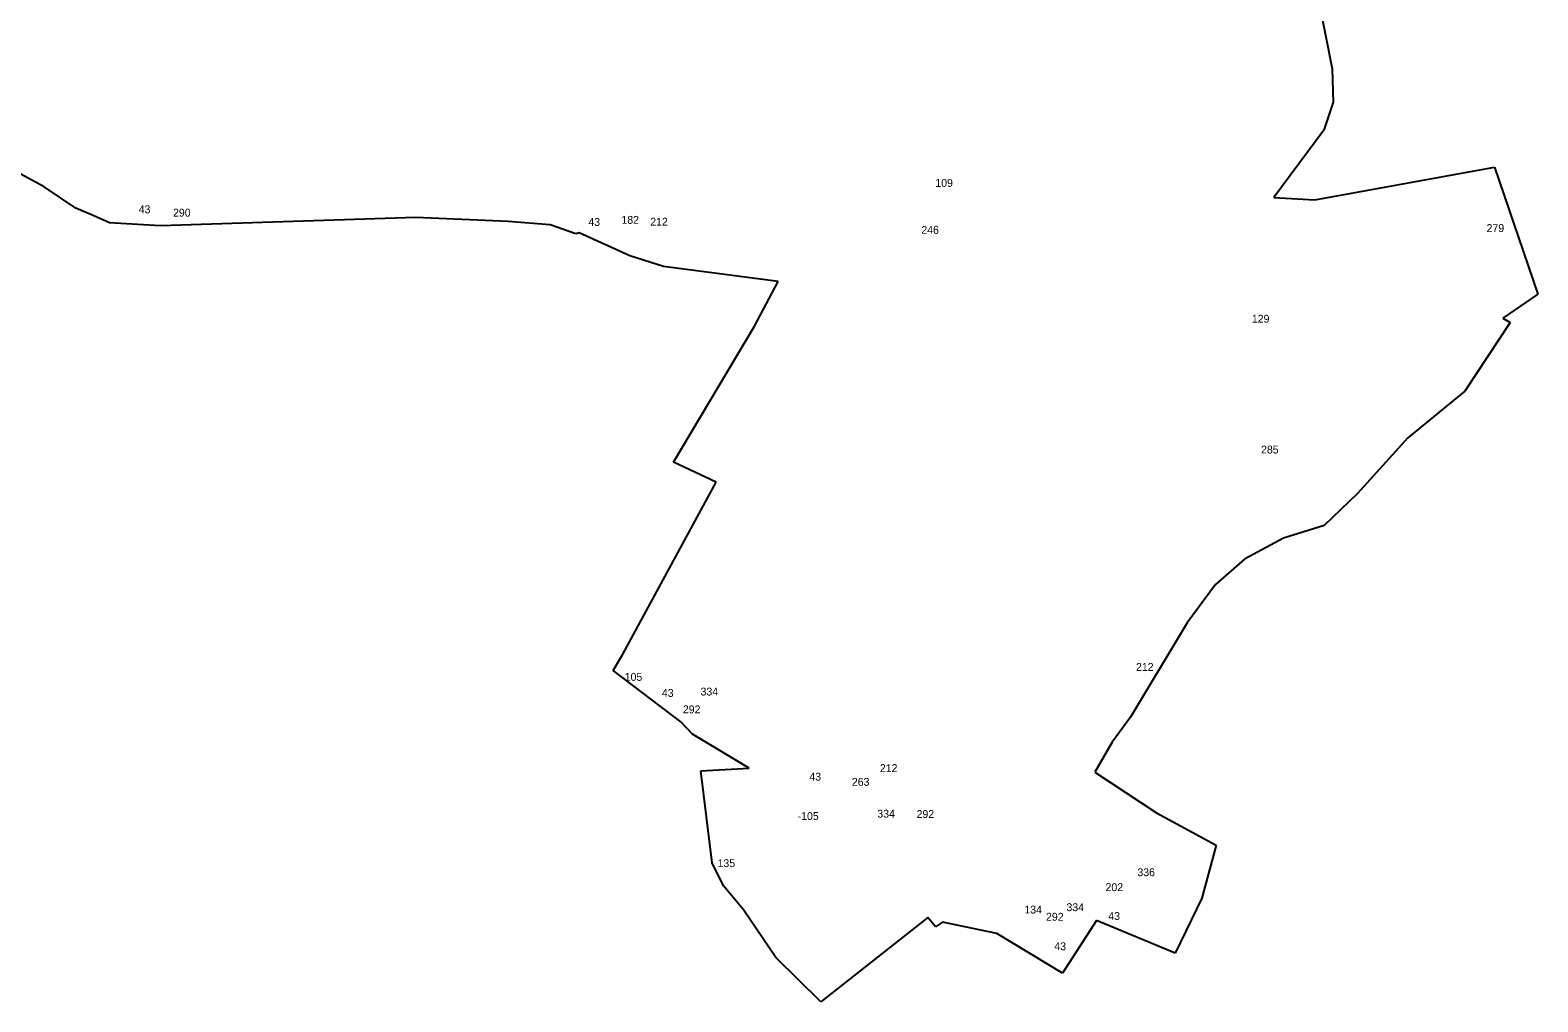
# Model space of a CAD drawing. Extents: x -780116 to -776974, y -980293 to -977147.
# Drawn here: x -778640 to -777427, y -980293 to -979511 of the extents above; entities that cross this region are included whole.
import ezdxf

# ---------------------------------------------------------------- set-up
doc = ezdxf.new("R2010")
doc.units = 0
doc.layers.add('Vrstva 15', color=7, linetype='Continuous')
doc.layers.add('Vrstva 24', color=7, linetype='Continuous')

msp = doc.modelspace()

# ---------------------------------------------------------------- linework, layer by layer
at = {"layer": 'Vrstva 15'}
for p, q in [((-777602.89, -979490.63), (-777592.69, -979542.23)), ((-777592.69, -979542.23), (-777591.82, -979569.04)), ((-777591.82, -979569.04), (-777599.39, -979591.42)), ((-777599.39, -979591.42), (-777639.46, -979645.78)), ((-778628.77, -979637.15), (-778699.86, -979598.82)), ((-777606.53, -979647.67), (-777462.01, -979621.3)), ((-777462.01, -979621.3), (-777427.18, -979723.33)), ((-778603.27, -979654.2), (-778628.77, -979637.15)), ((-778588.74, -979660.54), (-778603.27, -979654.2)), ((-777639.46, -979645.78), (-777606.53, -979647.67)), ((-778576.21, -979665.93), (-778588.74, -979660.54)), ((-778534.99, -979668.48), (-778576.21, -979665.93)), ((-778329.86, -979661.77), (-778534.99, -979668.48)), ((-778255.41, -979664.91), (-778329.86, -979661.77)), ((-778221.69, -979667.59), (-778255.41, -979664.91)), ((-778201.08, -979674.89), (-778221.69, -979667.59)), ((-778198.45, -979674.01), (-778201.08, -979674.89)), ((-778157.66, -979692.67), (-778198.45, -979674.01)), ((-778130.56, -979701.05), (-778157.66, -979692.67)), ((-778038.34, -979713.26), (-778130.56, -979701.05)), ((-778057.28, -979749.18), (-778038.34, -979713.26)), ((-777427.18, -979723.33), (-777455.45, -979742.86)), ((-778122.56, -979858.68), (-778057.28, -979749.18)), ((-777449.47, -979746.21), (-777486.03, -979801.53)), ((-777455.45, -979742.86), (-777449.47, -979746.21)), ((-777486.03, -979801.53), (-777531.7, -979838.88)), ((-777531.7, -979838.88), (-777572.14, -979883.69)), ((-778088.04, -979874.57), (-778122.56, -979858.68)), ((-778163.21, -980013.03), (-778088.04, -979874.57)), ((-777572.14, -979883.69), (-777599.16, -979909.56)), ((-777599.16, -979909.56), (-777631.73, -979919.62)), ((-777631.73, -979919.62), (-777663.2, -979936.6)), ((-777663.2, -979936.6), (-777686.51, -979956.94)), ((-777686.51, -979956.94), (-777709.24, -979987.76)), ((-777709.24, -979987.76), (-777754.84, -980063.63)), ((-778171.07, -980026.07), (-778163.21, -980013.03)), ((-778116.44, -980067.5), (-778171.07, -980026.07)), ((-778107.05, -980077.41), (-778116.44, -980067.5)), ((-777754.84, -980063.63), (-777769.55, -980083.67)), ((-778061.66, -980104.56), (-778107.05, -980077.41)), ((-777769.55, -980083.67), (-777783.54, -980107.79)), ((-778100.41, -980106.9), (-778061.66, -980104.56)), ((-778091.39, -980180.72), (-778100.41, -980106.9)), ((-777783.54, -980107.79), (-777734.01, -980140.52)), ((-777734.01, -980140.52), (-777685.89, -980166.64)), ((-777685.89, -980166.64), (-777697.58, -980209.29)), ((-778082.21, -980199.23), (-778091.39, -980180.72)), ((-778066.04, -980218.76), (-778082.21, -980199.23)), ((-777697.58, -980209.29), (-777718.93, -980253.63)), ((-778040.25, -980257.09), (-778066.04, -980218.76)), ((-777917.87, -980224.74), (-778003.83, -980292.65)), ((-777911.6, -980232.32), (-777917.87, -980224.74)), ((-777782.08, -980227.1), (-777809.62, -980269.63)), ((-777718.93, -980253.63), (-777782.08, -980227.1)), ((-777906.21, -980228.67), (-777911.6, -980232.32)), ((-777862.36, -980237.71), (-777906.21, -980228.67)), ((-777809.62, -980269.63), (-777862.36, -980237.71)), ((-778003.83, -980292.65), (-778040.25, -980257.09))]:
    msp.add_line(p, q, dxfattribs=at)

# ---------------------------------------------------------------- texts
at = {"layer": 'Vrstva 24'}
for s, p in [('109', (-777911.856, -979637.114)), ('43', (-778552.655, -979658.354)), ('290', (-778525.028, -979661.044)), ('43', (-778190.965, -979668.564)), ('182', (-778164.341, -979666.834)), ('212', (-778141.161, -979668.314)), ('246', (-777923.103, -979674.884)), ('279', (-777468.398, -979673.474)), ('129', (-777657.231, -979746.354)), ('285', (-777649.833, -979851.594)), ('212', (-777750.421, -980026.434)), ('-105', (-778164.519, -980034.434)), ('43', (-778131.795, -980047.324)), ('334', (-778100.703, -980046.244)), ('292', (-778114.923, -980060.574)), ('212', (-777956.441, -980107.814)), ('43', (-778013.175, -980114.674)), ('263', (-777978.973, -980118.864)), ('-105', (-778022.589, -980146.384)), ('334', (-777958.513, -980144.494)), ('292', (-777926.923, -980144.764)), ('135', (-778087.041, -980184.274)), ('336', (-777749.313, -980191.584)), ('202', (-777774.937, -980203.594)), ('134', (-777840.191, -980221.584)), ('334', (-777806.383, -980219.684)), ('292', (-777822.793, -980227.394)), ('43', (-777772.725, -980226.784)), ('43', (-777816.155, -980251.134))]:
    msp.add_text(s, height=6.336, dxfattribs=at).set_placement(p)

doc.saveas('drawing.dxf')
